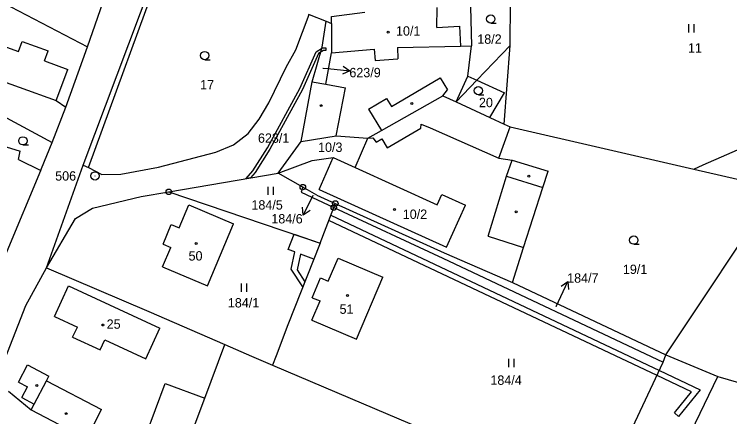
# Model space of a CAD drawing. Extents: x -743888 to -742027, y -1128394 to -1126768.
# Drawn here: x -742956.8 to -742827, y -1127574.7 to -1127501.6 of the extents above; entities that cross this region are included whole.
import ezdxf

# ---------------------------------------------------------------- set-up
doc = ezdxf.new("R2010")
doc.units = 0
for name, color, linetype in [('Vrstva 1', 7, 'Continuous'), ('Vrstva 16', 7, 'Continuous'), ('Vrstva 17', 7, 'Continuous'), ('Vrstva 18', 7, 'Continuous'), ('Vrstva 19', 7, 'Continuous'), ('Vrstva 24', 7, 'Continuous'), ('Vrstva 25', 7, 'Continuous'), ('Vrstva 3', 7, 'Continuous'), ('Vrstva 30', 7, 'Continuous'), ('Vrstva 37', 7, 'Continuous'), ('Vrstva 4', 7, 'Continuous'), ('Vrstva 52', 7, 'Continuous'), ('Vrstva 6', 7, 'Continuous')]:
    doc.layers.add(name, color=color, linetype=linetype)

msp = doc.modelspace()

# ---------------------------------------------------------------- linework, layer by layer
at = {"layer": 'Vrstva 1'}
for p, q in [((-742903.28, -1127501.66), (-742900.23, -1127502.88)), ((-742900.93, -1127507.59), (-742900.23, -1127502.88)), ((-742900.23, -1127502.88), (-742899.27, -1127503.27)), ((-742902.74, -1127513.85), (-742900.93, -1127507.59)), ((-742928.77, -1127533.84), (-742908.91, -1127530.44)), ((-742904.45, -1127532.98), (-742908.91, -1127530.44)), ((-742904.45, -1127532.98), (-742904.77, -1127533.92)), ((-742901.93, -1127534.42), (-742904.45, -1127532.98)), ((-742933.8, -1127534.7), (-742928.77, -1127533.84)), ((-742928.77, -1127533.84), (-742901.31, -1127543.14)), ((-742904.77, -1127533.92), (-742898.83, -1127536.68)), ((-742901.93, -1127534.42), (-742898.55, -1127535.95)), ((-742898.83, -1127536.68), (-742898.55, -1127535.95)), ((-742898.55, -1127535.95), (-742878.8, -1127544.89)), ((-742901.31, -1127543.14), (-742898.83, -1127536.68)), ((-742898.83, -1127536.68), (-742879.04, -1127545.88)), ((-742901.31, -1127543.14), (-742907.18, -1127557.98)), ((-742879.04, -1127545.88), (-742839.05, -1127564.77)), ((-742907.18, -1127557.98), (-742909.31, -1127563.59)), ((-742913.78, -1127563.64), (-742909.93, -1127565.28)), ((-742909.31, -1127563.59), (-742909.93, -1127565.28)), ((-742909.93, -1127565.28), (-742889.01, -1127574.21))]:
    msp.add_line(p, q, dxfattribs=at)
for points in [[(-742944.28, -1127528.98), (-742929.86, -1127490.53)], [(-742974.21, -1127491.49), (-742943.52, -1127507.49)], [(-742943.52, -1127507.49), (-742939.27, -1127495.28)], [(-742866.85, -1127507.25), (-742866.77, -1127499.38)], [(-742874.03, -1127500.28), (-742873.82, -1127507.33)], [(-742905.69, -1127508.04), (-742903.28, -1127501.66)], [(-742903.5, -1127501.56), (-742903.28, -1127501.66)], [(-742899.27, -1127503.27), (-742899.22, -1127501.99)], [(-742899.22, -1127501.99), (-742893.18, -1127501.21)], [(-742899.27, -1127503.27), (-742899.27, -1127508.59)], [(-742947.48, -1127518.45), (-742943.52, -1127507.49)], [(-742874.5, -1127512.82), (-742873.82, -1127507.33)], [(-742867.89, -1127521.56), (-742866.85, -1127507.25)], [(-742907.48, -1127511.22), (-742905.69, -1127508.04)], [(-742910.6, -1127517.69), (-742907.48, -1127511.22)], [(-742962.69, -1127512.44), (-742949.22, -1127517.23)], [(-742904.75, -1127524.72), (-742902.74, -1127513.85)], [(-742902.74, -1127513.85), (-742900.26, -1127514.3)], [(-742876.63, -1127517.52), (-742874.5, -1127512.82)], [(-742890.2, -1127522.7), (-742879.04, -1127516.41)], [(-742879.04, -1127516.41), (-742876.63, -1127517.52)], [(-742949.22, -1127517.23), (-742947.48, -1127518.45)], [(-742912.34, -1127520.62), (-742910.6, -1127517.69)], [(-742876.63, -1127517.52), (-742870.52, -1127520.34)], [(-742962.06, -1127518.33), (-742949.93, -1127524.86)], [(-742949.93, -1127524.86), (-742947.48, -1127518.45)], [(-742870.52, -1127520.34), (-742867.89, -1127521.56)], [(-742914.34, -1127523.24), (-742912.34, -1127520.62)], [(-742867.89, -1127521.56), (-742866.81, -1127522.06)], [(-742892.64, -1127524.08), (-742890.2, -1127522.7)], [(-742868.86, -1127527.7), (-742866.81, -1127522.06)], [(-742866.81, -1127522.06), (-742833.52, -1127529.71)], [(-742917.02, -1127525.28), (-742914.34, -1127523.24)], [(-742904.75, -1127524.72), (-742898.37, -1127523.69)], [(-742898.37, -1127523.69), (-742892.64, -1127524.08)], [(-742894.97, -1127529.41), (-742892.64, -1127524.08)], [(-742951.87, -1127529.63), (-742949.93, -1127524.86)], [(-742920.21, -1127526.66), (-742917.02, -1127525.28)], [(-742930.66, -1127529.38), (-742920.21, -1127526.66)], [(-742956.04, -1127527.94), (-742952.01, -1127529.96)], [(-742902.77, -1127528.16), (-742898.93, -1127527.6)], [(-742898.93, -1127527.6), (-742894.97, -1127529.41)], [(-742868.86, -1127527.7), (-742866.48, -1127528.08)], [(-742866.48, -1127528.08), (-742859.94, -1127530.06)], [(-742952.01, -1127529.96), (-742951.87, -1127529.63)], [(-742950.97, -1127547.61), (-742944.28, -1127528.98)], [(-742944.28, -1127528.98), (-742943.36, -1127529.4)], [(-742943.36, -1127529.4), (-742940.91, -1127530.67)], [(-742937.49, -1127530.65), (-742930.66, -1127529.38)], [(-742958.07, -1127544.59), (-742952.01, -1127529.96)], [(-742940.91, -1127530.67), (-742937.49, -1127530.65)], [(-742860.9, -1127533.04), (-742859.94, -1127530.06)], [(-742833.52, -1127529.71), (-742818.41, -1127533.18)], [(-742864.4, -1127543.94), (-742860.9, -1127533.04)], [(-742838.56, -1127563.45), (-742818.41, -1127533.18)], [(-742945.7, -1127538.65), (-742942.64, -1127536.81)], [(-742926.91, -1127540.37), (-742925.16, -1127536.21)], [(-742925.16, -1127536.21), (-742917.03, -1127539.62)], [(-742950.97, -1127547.61), (-742945.7, -1127538.65)], [(-742929.81, -1127543.36), (-742928.31, -1127539.78)], [(-742928.31, -1127539.78), (-742926.91, -1127540.37)], [(-742921.76, -1127550.89), (-742917.03, -1127539.62)], [(-742929.81, -1127543.36), (-742928.41, -1127543.95)], [(-742929.89, -1127547.48), (-742928.41, -1127543.95)], [(-742878.8, -1127544.89), (-742866.42, -1127550.29)], [(-742866.42, -1127550.29), (-742864.4, -1127543.94)], [(-742899.82, -1127550.06), (-742898.05, -1127545.88)], [(-742898.05, -1127545.88), (-742889.94, -1127549.3)], [(-742954.72, -1127554.49), (-742950.97, -1127547.61)], [(-742950.97, -1127547.61), (-742932.41, -1127555.57)], [(-742929.89, -1127547.48), (-742921.76, -1127550.89)], [(-742902.74, -1127553.05), (-742901.23, -1127549.47)], [(-742901.23, -1127549.47), (-742899.82, -1127550.06)], [(-742894.7, -1127560.58), (-742889.94, -1127549.3)], [(-742866.42, -1127550.29), (-742838.56, -1127563.45)], [(-742902.81, -1127557.15), (-742901.33, -1127553.64)], [(-742902.74, -1127553.05), (-742901.33, -1127553.64)], [(-742958.43, -1127564.08), (-742954.72, -1127554.49)], [(-742932.41, -1127555.57), (-742918.6, -1127561.55)], [(-742902.81, -1127557.15), (-742894.7, -1127560.58)], [(-742922.25, -1127571.32), (-742918.6, -1127561.55)], [(-742918.6, -1127561.55), (-742913.78, -1127563.64)], [(-742839.05, -1127564.77), (-742838.56, -1127563.45)], [(-742851.05, -1127590.28), (-742839.05, -1127564.77)], [(-742957.84, -1127570.04), (-742953.72, -1127573.43)], [(-742927.53, -1127585.44), (-742922.25, -1127571.32)], [(-742953.72, -1127573.43), (-742943.72, -1127578.66)], [(-742889.01, -1127574.21), (-742851.05, -1127590.28)]]:
    msp.add_lwpolyline(points, dxfattribs=at)
at = {"layer": 'Vrstva 16'}
for p, q in [((-742897.12, -1127511), (-742895.9, -1127511.87)), ((-742903.13, -1127537.25), (-742904.37, -1127538.1)), ((-742857.6, -1127550.97), (-742856.37, -1127550.1))]:
    msp.add_line(p, q, dxfattribs=at)
for points in [[(-742900.84, -1127511.38), (-742899.88, -1127511.47)], [(-742899.88, -1127511.47), (-742895.9, -1127511.87), (-742897.27, -1127512.49)], [(-742902.64, -1127534.49), (-742904.37, -1127538.1), (-742904.48, -1127536.6)], [(-742858.03, -1127553.74), (-742856.37, -1127550.1), (-742856.23, -1127551.59)], [(-742858.45, -1127554.67), (-742858.03, -1127553.74)]]:
    msp.add_lwpolyline(points, dxfattribs=at)
at = {"layer": 'Vrstva 24'}
for p, q in [((-742942.2, -1127530.95), (-742942.1, -1127530.95)), ((-742904.5, -1127532.98), (-742904.4, -1127532.98)), ((-742928.82, -1127533.84), (-742928.72, -1127533.84)), ((-742898.6, -1127535.95), (-742898.5, -1127535.95)), ((-742898.88, -1127536.68), (-742898.78, -1127536.68))]:
    msp.add_line(p, q, dxfattribs=at)
for centre, radius in [((-742942.15, -1127530.95), 0.756), ((-742928.77, -1127533.84), 0.499), ((-742904.45, -1127532.98), 0.499), ((-742898.55, -1127535.95), 0.499), ((-742898.83, -1127536.68), 0.499)]:
    msp.add_circle(centre, radius, dxfattribs=at)
at = {"layer": 'Vrstva 25'}
for p, q in [((-742870.34, -1127503.22), (-742869.34, -1127503.22)), ((-742834.46, -1127503.42), (-742834.46, -1127504.92)), ((-742833.46, -1127504.92), (-742833.46, -1127503.42)), ((-742922.25, -1127509.85), (-742921.25, -1127509.85)), ((-742872.59, -1127516.22), (-742871.59, -1127516.22)), ((-742955.24, -1127525.33), (-742954.24, -1127525.33)), ((-742910.78, -1127532.9), (-742910.78, -1127534.4)), ((-742909.78, -1127534.4), (-742909.78, -1127532.9)), ((-742844.4, -1127543.35), (-742843.4, -1127543.35)), ((-742915.63, -1127550.48), (-742915.63, -1127551.98)), ((-742914.63, -1127551.98), (-742914.63, -1127550.48)), ((-742867.11, -1127564.18), (-742867.11, -1127565.68)), ((-742866.11, -1127565.68), (-742866.11, -1127564.18))]:
    msp.add_line(p, q, dxfattribs=at)
for centre, radius in [((-742870.34, -1127502.47), 0.75), ((-742888.98, -1127504.86), 0.175), ((-742922.25, -1127509.1), 0.75), ((-742872.59, -1127515.47), 0.75), ((-742884.66, -1127517.81), 0.175), ((-742901.14, -1127518.19), 0.175), ((-742955.24, -1127524.58), 0.75), ((-742863.44, -1127531.01), 0.175), ((-742887.81, -1127537.03), 0.175), ((-742865.72, -1127537.45), 0.175), ((-742844.4, -1127542.6), 0.75), ((-742923.81, -1127543.23), 0.175), ((-742896.34, -1127552.66), 0.175), ((-742940.73, -1127558.01), 0.175), ((-742952.73, -1127568.97), 0.175), ((-742947.4, -1127574.1), 0.175)]:
    msp.add_circle(centre, radius, dxfattribs=at)
at = {"layer": 'Vrstva 3'}
for points in [[(-742880.13, -1127503.99), (-742880.06, -1127500.37)], [(-742899.27, -1127503.27), (-742899.22, -1127501.99)], [(-742899.22, -1127501.99), (-742893.18, -1127501.21)], [(-742969.62, -1127503.47), (-742956.03, -1127508.38)], [(-742899.27, -1127503.27), (-742899.27, -1127508.59)], [(-742880.13, -1127503.99), (-742876.02, -1127503.78)], [(-742876.02, -1127503.78), (-742875.83, -1127507.38)], [(-742956.03, -1127508.38), (-742955.38, -1127506.56)], [(-742955.38, -1127506.56), (-742950.68, -1127508.23)], [(-742887.27, -1127507.64), (-742875.83, -1127507.38)], [(-742951.35, -1127510.07), (-742950.68, -1127508.23)], [(-742899.27, -1127508.59), (-742891.5, -1127507.96)], [(-742891.5, -1127507.96), (-742891.34, -1127509.98)], [(-742887.27, -1127507.64), (-742887.23, -1127509.68)], [(-742951.35, -1127510.07), (-742947.07, -1127511.61)], [(-742891.34, -1127509.98), (-742887.23, -1127509.68)], [(-742962.69, -1127512.44), (-742949.22, -1127517.23)], [(-742949.22, -1127517.23), (-742947.07, -1127511.61)], [(-742901.48, -1127533.41), (-742898.93, -1127527.6)], [(-742898.93, -1127527.6), (-742894.97, -1127529.41)], [(-742894.97, -1127529.41), (-742880.07, -1127536.22)], [(-742901.48, -1127533.41), (-742878.35, -1127543.88)], [(-742880.07, -1127536.22), (-742879.21, -1127534.33)], [(-742879.21, -1127534.33), (-742874.94, -1127536.28)], [(-742926.91, -1127540.37), (-742925.16, -1127536.21)], [(-742925.16, -1127536.21), (-742917.03, -1127539.62)], [(-742878.35, -1127543.88), (-742874.94, -1127536.28)], [(-742929.81, -1127543.36), (-742928.31, -1127539.78)], [(-742928.31, -1127539.78), (-742926.91, -1127540.37)], [(-742921.76, -1127550.89), (-742917.03, -1127539.62)], [(-742929.81, -1127543.36), (-742928.41, -1127543.95)], [(-742929.89, -1127547.48), (-742928.41, -1127543.95)], [(-742899.82, -1127550.06), (-742898.05, -1127545.88)], [(-742898.05, -1127545.88), (-742889.94, -1127549.3)], [(-742929.89, -1127547.48), (-742921.76, -1127550.89)], [(-742902.74, -1127553.05), (-742901.23, -1127549.47)], [(-742901.23, -1127549.47), (-742899.82, -1127550.06)], [(-742894.7, -1127560.58), (-742889.94, -1127549.3)], [(-742949.53, -1127556.44), (-742946.97, -1127550.91)], [(-742946.97, -1127550.91), (-742930.37, -1127558.61)], [(-742902.81, -1127557.15), (-742901.33, -1127553.64)], [(-742902.74, -1127553.05), (-742901.33, -1127553.64)], [(-742949.53, -1127556.44), (-742945.36, -1127558.38)], [(-742902.81, -1127557.15), (-742894.7, -1127560.58)], [(-742946.22, -1127560.22), (-742945.36, -1127558.38)], [(-742932.94, -1127564.15), (-742930.37, -1127558.61)], [(-742946.22, -1127560.22), (-742941.23, -1127562.53)], [(-742941.23, -1127562.53), (-742940.37, -1127560.69)], [(-742940.37, -1127560.69), (-742932.94, -1127564.15)]]:
    msp.add_lwpolyline(points, dxfattribs=at)
at = {"layer": 'Vrstva 30'}
for points in [[(-742904.96, -1127515.05), (-742902.02, -1127508.4)], [(-742901.63, -1127508.75), (-742904.51, -1127515.27)], [(-742902.02, -1127508.4), (-742900.87, -1127507.68)], [(-742900.72, -1127508.18), (-742901.63, -1127508.75)], [(-742900.87, -1127507.68), (-742900.29, -1127507.71)], [(-742900.3, -1127508.21), (-742900.72, -1127508.18)], [(-742900.29, -1127507.71), (-742900.3, -1127508.21)], [(-742910.87, -1127525.82), (-742904.96, -1127515.05)], [(-742904.51, -1127515.27), (-742910.44, -1127526.07)], [(-742913.51, -1127530.05), (-742910.87, -1127525.82)], [(-742910.44, -1127526.07), (-742913.09, -1127530.32)], [(-742913.09, -1127530.32), (-742913.96, -1127531.31), (-742914.75, -1127531.44), (-742913.51, -1127530.05)], [(-742899.73, -1127539.03), (-742899.37, -1127538.09), (-742839.75, -1127566.27), (-742832.32, -1127569.78), (-742836.26, -1127574.59), (-742837.03, -1127573.96), (-742833.9, -1127570.14), (-742840.18, -1127567.17), (-742899.73, -1127539.03)], [(-742901.31, -1127543.14), (-742902.47, -1127546.07), (-742904.89, -1127545.14), (-742905.49, -1127547.97), (-742904.09, -1127550.16), (-742904.45, -1127551.09), (-742906.54, -1127547.87), (-742905.9, -1127544.75), (-742907.08, -1127544.3), (-742906.04, -1127541.54), (-742901.31, -1127543.14)]]:
    msp.add_lwpolyline(points, dxfattribs=at)
at = {"layer": 'Vrstva 37'}
for centre in [(-742888.98, -1127504.86), (-742887.81, -1127537.03), (-742923.81, -1127543.23), (-742896.34, -1127552.66), (-742940.73, -1127558.01)]:
    msp.add_circle(centre, 0.175, dxfattribs=at)
at = {"layer": 'Vrstva 4'}
for points in [[(-742943.36, -1127529.4), (-742929.27, -1127490.78)], [(-742880.13, -1127503.99), (-742880.06, -1127500.37)], [(-742969.62, -1127503.47), (-742956.03, -1127508.38)], [(-742880.13, -1127503.99), (-742876.02, -1127503.78)], [(-742876.02, -1127503.78), (-742875.83, -1127507.38)], [(-742956.03, -1127508.38), (-742955.38, -1127506.56)], [(-742955.38, -1127506.56), (-742950.68, -1127508.23)], [(-742887.27, -1127507.64), (-742875.83, -1127507.38)], [(-742875.83, -1127507.38), (-742873.82, -1127507.33)], [(-742951.35, -1127510.07), (-742950.68, -1127508.23)], [(-742899.27, -1127508.59), (-742891.5, -1127507.96)], [(-742891.5, -1127507.96), (-742891.34, -1127509.98)], [(-742887.27, -1127507.64), (-742887.23, -1127509.68)], [(-742951.35, -1127510.07), (-742947.07, -1127511.61)], [(-742891.34, -1127509.98), (-742887.23, -1127509.68)], [(-742949.22, -1127517.23), (-742947.07, -1127511.61)], [(-742888.38, -1127518.37), (-742879.51, -1127513.13)], [(-742879.51, -1127513.13), (-742878.21, -1127515.33)], [(-742874.5, -1127512.82), (-742872.86, -1127513.56)], [(-742872.86, -1127513.56), (-742867.86, -1127515.85)], [(-742900.26, -1127514.3), (-742896.68, -1127514.94)], [(-742898.37, -1127523.69), (-742896.68, -1127514.94)], [(-742879.04, -1127516.41), (-742878.21, -1127515.33)], [(-742870.52, -1127520.34), (-742867.86, -1127515.85)], [(-742892.51, -1127518.82), (-742889.25, -1127516.91)], [(-742889.25, -1127516.91), (-742888.38, -1127518.37)], [(-742892.51, -1127518.82), (-742890.2, -1127522.7)], [(-742883.01, -1127522.3), (-742882.95, -1127521.53)], [(-742882.95, -1127521.53), (-742881.35, -1127522.23)], [(-742889.16, -1127525.82), (-742883.01, -1127522.3)], [(-742881.35, -1127522.23), (-742868.86, -1127527.7)], [(-742892.64, -1127524.08), (-742891.73, -1127524.06)], [(-742891.73, -1127524.06), (-742891.16, -1127524.8)], [(-742891.16, -1127524.8), (-742890.14, -1127524.19)], [(-742890.14, -1127524.19), (-742889.16, -1127525.82)], [(-742901.48, -1127533.41), (-742898.93, -1127527.6)], [(-742867.5, -1127531), (-742866.48, -1127528.08)], [(-742894.97, -1127529.41), (-742880.07, -1127536.22)], [(-742870.82, -1127541.91), (-742867.5, -1127531)], [(-742867.5, -1127531), (-742860.9, -1127533.04)], [(-742901.48, -1127533.41), (-742878.35, -1127543.88)], [(-742880.07, -1127536.22), (-742879.21, -1127534.33)], [(-742879.21, -1127534.33), (-742874.94, -1127536.28)], [(-742878.35, -1127543.88), (-742874.94, -1127536.28)], [(-742870.82, -1127541.91), (-742864.4, -1127543.94)], [(-742949.53, -1127556.44), (-742946.97, -1127550.91)], [(-742946.97, -1127550.91), (-742930.37, -1127558.61)], [(-742949.53, -1127556.44), (-742945.36, -1127558.38)], [(-742946.22, -1127560.22), (-742945.36, -1127558.38)], [(-742932.94, -1127564.15), (-742930.37, -1127558.61)], [(-742946.22, -1127560.22), (-742941.23, -1127562.53)], [(-742941.23, -1127562.53), (-742940.37, -1127560.69)], [(-742940.37, -1127560.69), (-742932.94, -1127564.15)], [(-742956.04, -1127568.39), (-742954.4, -1127565.26)], [(-742954.4, -1127565.26), (-742950.51, -1127567.29)], [(-742950.95, -1127568.13), (-742950.51, -1127567.29)], [(-742956.04, -1127568.39), (-742954.4, -1127569.25)], [(-742953.17, -1127572.37), (-742950.95, -1127568.13)], [(-742950.95, -1127568.13), (-742940.95, -1127573.36)], [(-742955.42, -1127571.19), (-742954.4, -1127569.25)], [(-742934.7, -1127582.76), (-742929.42, -1127568.64)], [(-742929.42, -1127568.64), (-742922.25, -1127571.32)], [(-742955.42, -1127571.19), (-742953.17, -1127572.37)], [(-742953.72, -1127573.43), (-742953.17, -1127572.37)], [(-742943.72, -1127578.66), (-742940.95, -1127573.36)]]:
    msp.add_lwpolyline(points, dxfattribs=at)
at = {"layer": 'Vrstva 52'}
for points in [[(-742972.89, -1127572.54), (-742971.19, -1127569.17), (-742967.51, -1127562.65), (-742960.97, -1127550.69), (-742958.07, -1127544.59), (-742952.01, -1127529.96), (-742951.87, -1127529.63), (-742949.93, -1127524.86), (-742947.48, -1127518.45), (-742943.52, -1127507.49), (-742939.27, -1127495.28), (-742928.77, -1127471.57), (-742930.03, -1127470.75), (-742926.01, -1127462.54), (-742919.56, -1127450.77), (-742911.88, -1127437.64), (-742907.65, -1127433.29), (-742900.6, -1127419.3), (-742892.14, -1127404.73), (-742890.15, -1127399.92)], [(-742965.26, -1127573.48), (-742964.75, -1127572.6), (-742958.43, -1127564.08), (-742954.72, -1127554.49), (-742950.97, -1127547.61), (-742944.28, -1127528.98), (-742929.86, -1127490.53), (-742926.08, -1127481.57), (-742925.07, -1127479.17), (-742918.99, -1127466.07), (-742914.39, -1127456.16), (-742910.36, -1127448.54), (-742907.43, -1127444.81), (-742902.44, -1127441.06), (-742891.64, -1127420.53), (-742883.68, -1127406.25)]]:
    msp.add_lwpolyline(points, dxfattribs=at)
at = {"layer": 'Vrstva 6'}
for points in [[(-742872.86, -1127513.56), (-742866.85, -1127507.25)], [(-742900.26, -1127514.3), (-742899.27, -1127508.59)], [(-742876.63, -1127517.52), (-742872.86, -1127513.56)], [(-742831.78, -1127528.92), (-742807.02, -1127518.12)], [(-742963.44, -1127524.1), (-742955.76, -1127526.44)], [(-742908.91, -1127530.44), (-742904.75, -1127524.72)], [(-742956.04, -1127527.94), (-742955.76, -1127526.44)], [(-742908.91, -1127530.44), (-742902.77, -1127528.16)], [(-742833.52, -1127529.71), (-742831.78, -1127528.92)], [(-742942.64, -1127536.81), (-742933.8, -1127534.7)], [(-742838.56, -1127563.45), (-742829.14, -1127567.37)], [(-742842.01, -1127594.12), (-742829.14, -1127567.37)], [(-742829.14, -1127567.37), (-742823.54, -1127569.02)]]:
    msp.add_lwpolyline(points, dxfattribs=at)

# ---------------------------------------------------------------- texts
at = {"layer": 'Vrstva 16'}
for s, p in [('623/9', (-742896, -1127513.04)), ('184/6', (-742910.16, -1127539.57)), ('184/7', (-742856.48, -1127550.33))]:
    msp.add_text(s, height=1.7, dxfattribs=at).set_placement(p)
at = {"layer": 'Vrstva 17'}
msp.add_text('506', height=1.7, dxfattribs=at).set_placement((-742949.38, -1127531.8))
at = {"layer": 'Vrstva 18'}
for s, height, p in [('18/2', 1.7, (-742872.79, -1127506.96)), ('11', 1.7, (-742834.56, -1127508.56)), ('623/9', 0.1, (-742901.03, -1127511.38)), ('17', 1.7, (-742923.08, -1127515.25)), ('20', 1.7, (-742872.49, -1127518.47)), ('623/1', 1.7, (-742912.59, -1127524.93)), ('184/6', 0.1, (-742902.64, -1127534.49)), ('184/5', 1.7, (-742913.77, -1127537.06)), ('19/1', 1.7, (-742846.37, -1127548.75)), ('184/1', 1.7, (-742918.05, -1127554.83)), ('184/7', 0.1, (-742858.45, -1127554.67)), ('184/4', 1.7, (-742870.41, -1127568.87))]:
    msp.add_text(s, height=height, dxfattribs=at).set_placement(p)
at = {"layer": 'Vrstva 19'}
for s, p in [('10/1', (-742887.54, -1127505.48)), ('10/3', (-742901.68, -1127526.59)), ('10/2', (-742886.31, -1127538.75)), ('50', (-742925.18, -1127546.31)), ('51', (-742897.78, -1127555.98)), ('25', (-742940.04, -1127558.69))]:
    msp.add_text(s, height=1.7, dxfattribs=at).set_placement(p)

doc.saveas('drawing.dxf')
